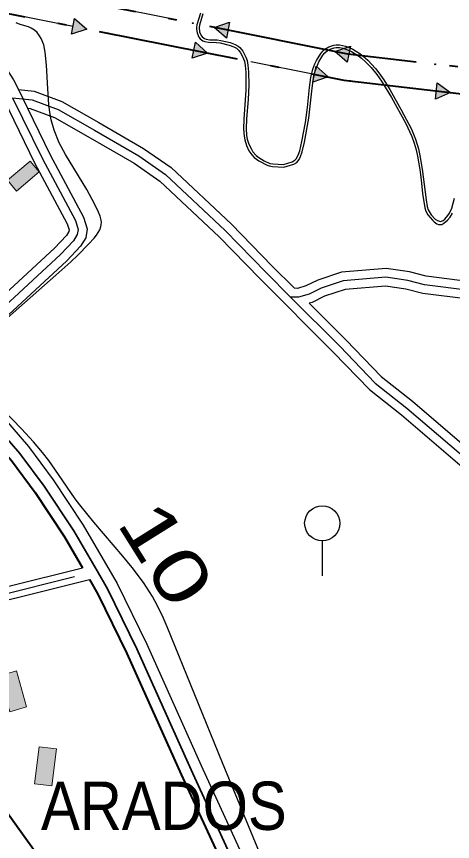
# Model space of a CAD drawing. Extents: x -64005 to -55000, y -89025 to -80000.
# Drawn here: x -61851 to -61355, y -84506 to -83567 of the extents above; entities that cross this region are included whole.
import ezdxf
from ezdxf.enums import TextEntityAlignment as Align

# ---------------------------------------------------------------- set-up
doc = ezdxf.new("R2010")
doc.units = 0
doc.header["$LTSCALE"] = 32
doc.linetypes.add('DOT_DASHED', pattern=[7.7, 5, -1.2, 0.3, -1.2])
doc.linetypes.add('LONG_DASHED', pattern=[7.5, 6, -1.5])
for name, color, linetype, lineweight in [('18', 7, 'Continuous', 25), ('21', 7, 'Continuous', 25), ('24', 7, 'Continuous', 25), ('32', 7, 'Continuous', 25), ('39', 7, 'LONG_DASHED', 25), ('5', 7, 'Continuous', 40), ('6', 7, 'Continuous', 25), ('7', 7, 'Continuous', 13), ('8', 7, 'Continuous', 25)]:
    doc.layers.add(name, color=color, linetype=linetype, lineweight=lineweight)
doc.layers.add('30', color=7, linetype='Continuous')
doc.layers.add('36', color=7, linetype='Continuous')

msp = doc.modelspace()

# ---------------------------------------------------------------- hatches: boundary and pattern name
at = {"layer": '18'}
for points in [[(-61784.61, -83569.37), (-61770.7, -83581.57), (-61788.22, -83587.52)], [(-61611.89, -83591.96), (-61625.8, -83579.76), (-61608.28, -83573.81)], [(-61647.29, -83596.65), (-61633.38, -83608.85), (-61650.9, -83614.8)], [(-61474.57, -83619.23), (-61488.48, -83607.04), (-61470.97, -83601.09)], [(-61509.98, -83623.93), (-61496.07, -83636.12), (-61513.58, -83642.08)], [(-61372.08, -83642.85), (-61357.25, -83653.91), (-61374.24, -83661.22)]]:
    msp.add_hatch(color=256, dxfattribs=at).paths.add_polyline_path(points)
at = {"layer": '7'}
for points in [[(-61835.14, -83731.85), (-61861.18, -83753.71), (-61850.9, -83765.97), (-61824.86, -83744.11)], [(-61869.95, -84317.44), (-61858.52, -84358.38), (-61839.25, -84353), (-61850.68, -84312.06)], [(-61824.92, -84398.23), (-61830.35, -84440.38), (-61810.52, -84442.93), (-61805.09, -84400.78)]]:
    msp.add_hatch(color=256, dxfattribs=at).paths.add_polyline_path(points)

# ---------------------------------------------------------------- linework, layer by layer
at = {"layer": '18'}
for p, q in [((-61674.84, -83570.02), (-61747.4, -83555.6)), ((-61858.98, -83564.03), (-61786.41, -83578.45)), ((-61537.53, -83597.3), (-61610.09, -83582.88)), ((-61721.66, -83591.31), (-61649.1, -83605.73)), ((-61399.29, -83618.74), (-61472.76, -83610.08)), ((-61584.34, -83618.59), (-61511.78, -83633)), ((-61446.63, -83643.38), (-61373.16, -83652.03)), ((-61875.81, -84453.2), (-61832.54, -84513.2))]:
    msp.add_line(p, q, dxfattribs=at)
at = {"layer": '18', "linetype": 'DOT_DASHED', "lineweight": 40}
for points in [[(-62511.18, -83419.68), (-62511.65, -83442.16), (-62269.37, -83547.46), (-62236.29, -83546.11), (-61998.23, -83536.37), (-61478.42, -83639.63), (-61155.09, -83677.73), (-60626.09, -83739.21), (-60379.64, -83770.49), (-59836.37, -83832.74), (-59632.07, -83878.3), (-59482.83, -83910.88), (-59245.7, -83916.4), (-59157.46, -83918.46), (-58274.27, -84022.41)], [(-59176.97, -83888), (-59290.14, -83885.36), (-59657.06, -83841.98), (-59831.38, -83803.11), (-60376.04, -83740.71), (-60622.47, -83709.43), (-61151.6, -83647.93), (-61473.73, -83609.97), (-61992.38, -83506.94), (-61993.6, -83506.74), (-62420.8, -83437.27), (-62481.72, -83419.68)], [(-62324.62, -83917.41), (-62289.57, -83955.78), (-62116.42, -84145.34), (-62026.35, -84244.41), (-61697.45, -84700.56), (-61690.71, -84709.91), (-61594.06, -84786.87), (-61523.16, -84843.33), (-61486.06, -84864.82), (-61461.2, -84916.75), (-61338.44, -85039.79), (-61305.54, -85111.47), (-61281.78, -85163.54), (-61242.66, -85254.24), (-61364.04, -85330.31)]]:
    msp.add_lwpolyline(points, dxfattribs=at)
at = {"layer": '18'}
for points in [[(-61784.61, -83569.37), (-61770.7, -83581.57), (-61788.22, -83587.52)], [(-61611.89, -83591.96), (-61625.8, -83579.76), (-61608.28, -83573.81)], [(-61647.29, -83596.65), (-61633.38, -83608.85), (-61650.9, -83614.8)], [(-61474.57, -83619.23), (-61488.48, -83607.04), (-61470.97, -83601.09)], [(-61509.98, -83623.93), (-61496.07, -83636.12), (-61513.58, -83642.08)], [(-61372.08, -83642.85), (-61357.25, -83653.91), (-61374.24, -83661.22)]]:
    msp.add_lwpolyline(points, close=True, dxfattribs=at)
for centre in [(-61650.32, -83574.89), (-61746.18, -83586.44), (-61513, -83602.17), (-61608.86, -83613.72), (-61374.46, -83621.67), (-61471.46, -83640.45)]:
    msp.add_circle(centre, 0.5, dxfattribs=at)
at = {"layer": '21'}
for points in [[(-62310.06, -84367.78), (-62225.03, -84335.73), (-62096.36, -84288.12), (-62010.59, -84254.44), (-61941.97, -84235.9), (-61775.66, -84194.55)], [(-62306.01, -84382.29), (-62219.79, -84349.79), (-62091.02, -84302.14), (-62005.87, -84268.7), (-61938.21, -84250.42), (-61767.83, -84208.06)]]:
    msp.add_lwpolyline(points, dxfattribs=at)
at = {"layer": '24'}
for points in [[(-61641.6, -83563.34), (-61645.72, -83576.85), (-61646.19, -83579.82), (-61646.16, -83581.86), (-61645.38, -83585.92), (-61643.35, -83590.73), (-61641.83, -83592.8), (-61638.72, -83595.03), (-61636.56, -83595.79), (-61632.19, -83596.56), (-61623.39, -83596.87), (-61619.05, -83597.42), (-61608.71, -83599.85), (-61603.61, -83601.67), (-61600.62, -83603.4), (-61597.84, -83606.02), (-61595.95, -83608.59), (-61593.55, -83612.79), (-61591.44, -83618.16), (-61590.46, -83623.23), (-61589.91, -83630.63), (-61589.77, -83650.95), (-61592.1, -83684.07), (-61592.48, -83695.11), (-61591.94, -83703.61), (-61591.16, -83707.79), (-61589.25, -83713.97), (-61586.34, -83720.03), (-61583.17, -83724.74), (-61580.36, -83727.68), (-61575.07, -83731.48), (-61565.7, -83736.39), (-61563.33, -83737.32), (-61559.63, -83738.03), (-61546.52, -83738.63), (-61535.39, -83735.14), (-61532.05, -83733.25), (-61529.17, -83729.87), (-61527.59, -83726.68), (-61525.77, -83721.28), (-61523.13, -83710.35), (-61518.28, -83682.81), (-61514.5, -83648.81), (-61512.42, -83634.39), (-61510.8, -83628.37), (-61508.54, -83622.54), (-61506.69, -83618.73), (-61502.17, -83611.22), (-61499.88, -83608.49), (-61496.86, -83606.14), (-61494.05, -83604.59), (-61489.34, -83602.91), (-61486.97, -83602.53), (-61483.46, -83602.61), (-61479.33, -83603.43), (-61474.22, -83605.12), (-61469.7, -83607.29), (-61461.84, -83612.05), (-61458.24, -83614.68), (-61453.2, -83619.19), (-61447.46, -83625.32), (-61440.89, -83633.31), (-61435.56, -83640.96), (-61424.27, -83659.57), (-61407.98, -83689.16), (-61401.08, -83703.99), (-61398.34, -83711.51), (-61396.3, -83718.9), (-61394.69, -83726.38), (-61392.09, -83741.45), (-61390.51, -83753.12), (-61388.88, -83768.75), (-61386.37, -83784.89), (-61385.06, -83788.94), (-61382.95, -83792.97), (-61377.72, -83799.21), (-61375.71, -83801.01), (-61372.65, -83803.07), (-61370.62, -83803.88), (-61368.15, -83804.1), (-61366.95, -83803.84), (-61364.53, -83802.65), (-61360.58, -83799.22), (-61357.61, -83795.75), (-61354.68, -83791.08)], [(-61812.8, -83676.13), (-61813.81, -83667.3), (-61815.28, -83649.6), (-61816.62, -83622.65), (-61817.98, -83608.03), (-61819.83, -83599.43), (-61822.76, -83592.14), (-61824.57, -83589.13), (-61827.34, -83585.66), (-61830.39, -83582.84), (-61834.07, -83580.48), (-61837.14, -83579.15), (-61846.59, -83576.39), (-61851.17, -83574.65)], [(-61897.15, -83941.8), (-61805.84, -83861.81), (-61789.09, -83846.65), (-61780.91, -83838.82), (-61768.69, -83826.54), (-61762.45, -83819.7), (-61759.58, -83816.01), (-61756.13, -83810.24), (-61754.69, -83806.31), (-61754.3, -83804.33), (-61754.2, -83801.35), (-61754.48, -83799.14), (-61755.68, -83794.65), (-61757.48, -83790.13), (-61761.76, -83781.2), (-61770.93, -83764.05), (-61795.19, -83724.49), (-61802.27, -83710.91), (-61808.02, -83696.69), (-61811.27, -83684.91), (-61812.8, -83676.13)], [(-61512.39, -84668.44), (-61616.3, -84416.57), (-61679.27, -84261.67), (-61683.75, -84251.29), (-61689.91, -84238.57), (-61696.03, -84227.42), (-61706.34, -84211.3), (-61719.05, -84194.33), (-61729.78, -84181.24), (-61762.89, -84142.85), (-61778.75, -84123.14), (-61783.95, -84116.09), (-61807.1, -84082.25), (-61813.9, -84072.71), (-61821.01, -84063.43), (-61831.32, -84051.33), (-61844.97, -84036.62), (-61887.06, -83993.43)]]:
    msp.add_lwpolyline(points, dxfattribs=at)
at = {"layer": '32'}
msp.add_line((-61502.98, -84163.97), (-61502.98, -84203.97), dxfattribs=at)
msp.add_circle((-61502.98, -84143.97), 20, dxfattribs=at)
at = {"layer": '39', "linetype": 'Continuous'}
msp.add_lwpolyline([(-61855.17, -83659.93), (-61821.24, -83729.37), (-61783.75, -83799.46), (-61780.49, -83809.51), (-61781.58, -83815.48), (-61785.92, -83822.55), (-61800.59, -83838.04), (-61937.61, -83964.71)], dxfattribs=at)
at = {"layer": '39'}
for points in [[(-61855.17, -83659.93), (-61832.81, -83662.11), (-61803.45, -83673.22), (-61761.91, -83696.76), (-61711.64, -83725.87), (-61681.22, -83747.03), (-61613.23, -83810.8), (-61566.93, -83858.43), (-61538.9, -83886.55)], [(-61335.59, -83879.01), (-61386.67, -83872.68), (-61405.72, -83867.66), (-61430.59, -83863.95), (-61479.01, -83867.93), (-61504.14, -83876.4), (-61517.9, -83883.28), (-61529.82, -83886.72), (-61538.9, -83886.55)], [(-61538.9, -83886.55), (-61483.07, -83942.56), (-61442.59, -83984.37), (-61406.61, -84012.93), (-61334.65, -84074.57), (-61284.2, -84117.01)]]:
    msp.add_lwpolyline(points, dxfattribs=at)
at = {"layer": '39', "lineweight": 35}
for points in [[(-61937.61, -83964.71), (-61901.46, -84001.74), (-61846.8, -84064.58), (-61819.47, -84101.79), (-61785.51, -84152.63), (-61759.11, -84198.16)], [(-61759.11, -84198.16), (-61747.26, -84218.59), (-61713.76, -84286.81), (-61652.11, -84424.71), (-61604.11, -84529.16), (-61571.05, -84601.09), (-61492.2, -84778.18), (-61449.44, -84868.72), (-61423.67, -84926.15)]]:
    msp.add_lwpolyline(points, dxfattribs=at)
at = {"layer": '39', "linetype": 'DOT_DASHED'}
msp.add_lwpolyline([(-62317.43, -84378.58), (-62222.41, -84342.76), (-62093.69, -84295.13), (-62008.23, -84261.57), (-61940.09, -84243.16), (-61759.11, -84198.16)], dxfattribs=at)
at = {"layer": '5'}
for points in [[(-61958.63, -83962.32), (-61947.89, -83972.08), (-61910.66, -84010.22), (-61856.57, -84072.39), (-61829.71, -84108.96), (-61796.14, -84159.24), (-61775.66, -84194.55)], [(-61767.83, -84208.06), (-61758.29, -84224.5), (-61725.08, -84292.12), (-61663.5, -84429.87), (-61615.47, -84534.38), (-61582.44, -84606.24), (-61503.57, -84783.39), (-61460.8, -84873.95), (-61438.89, -84922.79)]]:
    msp.add_lwpolyline(points, dxfattribs=at)
at = {"layer": '5', "lineweight": 25}
msp.add_lwpolyline([(-61921.45, -83963.38), (-61892.26, -83993.26), (-61837.03, -84056.77), (-61809.23, -84094.61), (-61774.89, -84146.01), (-61736.23, -84212.69), (-61702.44, -84281.49), (-61640.72, -84419.54), (-61592.75, -84523.94), (-61559.66, -84595.94), (-61480.84, -84772.97), (-61438.08, -84863.49), (-61360.14, -85037.25), (-61330.59, -85098.87), (-61284.67, -85202.61), (-61254.81, -85271.39), (-61222.43, -85336.52), (-61199.1, -85368.34), (-61171.27, -85400.86), (-61026.61, -85531.51), (-60932.39, -85613.21), (-60849.5, -85686.73), (-60673.76, -85842.88)], dxfattribs=at)
at = {"layer": '6'}
msp.add_line((-61848.64, -83650.52), (-61838.33, -83671.62), dxfattribs=at)
for points in [[(-61895.94, -83588.55), (-61864.33, -83623.31), (-61854.05, -83639.44), (-61848.64, -83650.52)], [(-61910.03, -83602.81), (-61880.27, -83635.49), (-61871.53, -83649.24), (-61830.14, -83733.92), (-61792.99, -83803.39), (-61790.78, -83810.2), (-61791.08, -83811.84), (-61793.9, -83816.43), (-61807.62, -83830.92), (-61935.74, -83949.36)], [(-61838.33, -83671.62), (-61812.34, -83724.82), (-61774.51, -83795.53), (-61770.2, -83808.82), (-61772.08, -83819.12), (-61777.94, -83828.67), (-61793.56, -83845.16), (-61921.45, -83963.38)]]:
    msp.add_lwpolyline(points, dxfattribs=at)
at = {"layer": '7', "lineweight": 25}
for points in [[(-61638.72, -83564.21), (-61642.7, -83577.28), (-61643.1, -83579.78), (-61642.42, -83584.89), (-61640.79, -83588.76), (-61639.57, -83590.42), (-61637.07, -83592.21), (-61635.03, -83592.93), (-61630.9, -83593.66), (-61622.57, -83593.95), (-61618.47, -83594.47), (-61607.53, -83597.04), (-61602.13, -83598.96), (-61598.72, -83600.93), (-61596.75, -83602.63), (-61593.4, -83606.85), (-61589.77, -83613.66), (-61588.53, -83617.17), (-61587.48, -83622.63), (-61586.92, -83630.24), (-61586.64, -83645.46), (-61587.42, -83661.9), (-61589.08, -83683.81), (-61589.46, -83694.77), (-61588.94, -83702.84), (-61588.21, -83706.81), (-61586.4, -83712.67), (-61583.63, -83718.42), (-61581.85, -83721.25), (-61578.08, -83725.54), (-61575.24, -83727.75), (-61568.89, -83731.39), (-61562.42, -83734.4), (-61559.02, -83735.05), (-61546.91, -83735.61), (-61537.05, -83732.52), (-61534.15, -83730.88), (-61532.56, -83729.22), (-61530.29, -83725.18), (-61528.56, -83720.06), (-61526.06, -83709.69), (-61522.12, -83687.99), (-61519.84, -83670.95), (-61517.45, -83648.11), (-61515.92, -83636.72), (-61513.64, -83627.23), (-61511.28, -83621.16)], [(-61511.28, -83621.16), (-61509.35, -83617.19), (-61504.65, -83609.38), (-61502.03, -83606.25), (-61500.03, -83604.55), (-61495.35, -83601.78), (-61489.97, -83599.86), (-61487.25, -83599.43), (-61483.24, -83599.52), (-61476.53, -83601.04), (-61473.22, -83602.24), (-61468.31, -83604.59), (-61460.12, -83609.55), (-61456.37, -83612.29), (-61451.12, -83616.99), (-61442.49, -83626.47), (-61438.54, -83631.43), (-61433.09, -83639.25), (-61426.15, -83650.47), (-61413.08, -83673.33), (-61401.57, -83695.34), (-61396.74, -83706.85), (-61393.4, -83718.06), (-61391.77, -83725.65), (-61389.13, -83740.94), (-61384.9, -83775.87), (-61383.53, -83783.65), (-61382.31, -83787.43), (-61380.34, -83791.18), (-61378.99, -83793.06), (-61374.35, -83797.9), (-61371.89, -83799.55), (-61369.46, -83800.36), (-61368.28, -83800.38), (-61365.47, -83799.26), (-61363.62, -83797.79), (-61360.11, -83793.9), (-61358.23, -83791.16), (-61355.69, -83785.53), (-61352.56, -83774.2)]]:
    msp.add_lwpolyline(points, dxfattribs=at)
at = {"layer": '7'}
for points in [[(-61835.14, -83731.85), (-61861.18, -83753.71), (-61850.9, -83765.97), (-61824.86, -83744.11)], [(-61869.95, -84317.44), (-61858.52, -84358.38), (-61839.25, -84353), (-61850.68, -84312.06)], [(-61824.92, -84398.23), (-61830.35, -84440.38), (-61810.52, -84442.93), (-61805.09, -84400.78)]]:
    msp.add_lwpolyline(points, close=True, dxfattribs=at)
at = {"layer": '8'}
for points in [[(-61848.64, -83650.52), (-61830.52, -83652.29), (-61799.19, -83664.13), (-61756.94, -83688.08), (-61706.27, -83717.42), (-61674.91, -83739.24), (-61606.22, -83803.66), (-61559.8, -83851.42), (-61534.68, -83876.62)], [(-61336.66, -83888.95), (-61388.57, -83882.52), (-61407.74, -83877.47), (-61430.92, -83874.01), (-61476.97, -83877.8), (-61500.29, -83885.65), (-61514.25, -83892.63), (-61517.71, -83893.63)], [(-61517.71, -83893.63), (-61475.94, -83935.55), (-61435.86, -83976.94), (-61400.25, -84005.21), (-61328.17, -84066.95), (-61279.65, -84107.77)]]:
    msp.add_lwpolyline(points, dxfattribs=at)
at = {"layer": '8', "linetype": 'LONG_DASHED'}
for points in [[(-61838.33, -83671.62), (-61835.1, -83671.93), (-61807.71, -83682.3), (-61766.88, -83705.44), (-61717.01, -83734.32), (-61687.53, -83754.83), (-61620.24, -83817.94), (-61574.06, -83865.44), (-61490.2, -83949.57), (-61449.32, -83991.8), (-61412.97, -84020.65), (-61341.12, -84082.19), (-61299.34, -84117.35)], [(-61334.52, -83869.07), (-61384.77, -83862.83), (-61403.7, -83857.85), (-61430.26, -83853.89), (-61481.05, -83858.06), (-61507.99, -83867.15), (-61521.55, -83873.93), (-61531.14, -83876.69), (-61534.68, -83876.62)]]:
    msp.add_lwpolyline(points, dxfattribs=at)

# ---------------------------------------------------------------- texts
at = {"layer": '30', "width": 1.35}
msp.add_text('10', height=60, rotation=301.977, dxfattribs=at).set_placement((-61737.71, -84143.52))
at = {"layer": '36', "width": 0.9}
msp.add_text('ARADOS', height=55, dxfattribs=at).set_placement((-61683.11, -84492.94), align=Align.CENTER)

doc.saveas('drawing.dxf')
